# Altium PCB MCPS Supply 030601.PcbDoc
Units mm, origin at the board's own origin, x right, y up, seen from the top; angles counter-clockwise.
Board outline 142.99 x 138.8 mm, 2 copper layers (Top Layer, Bottom Layer); 73 components, 47 nets, 185 pads, 18 vias.
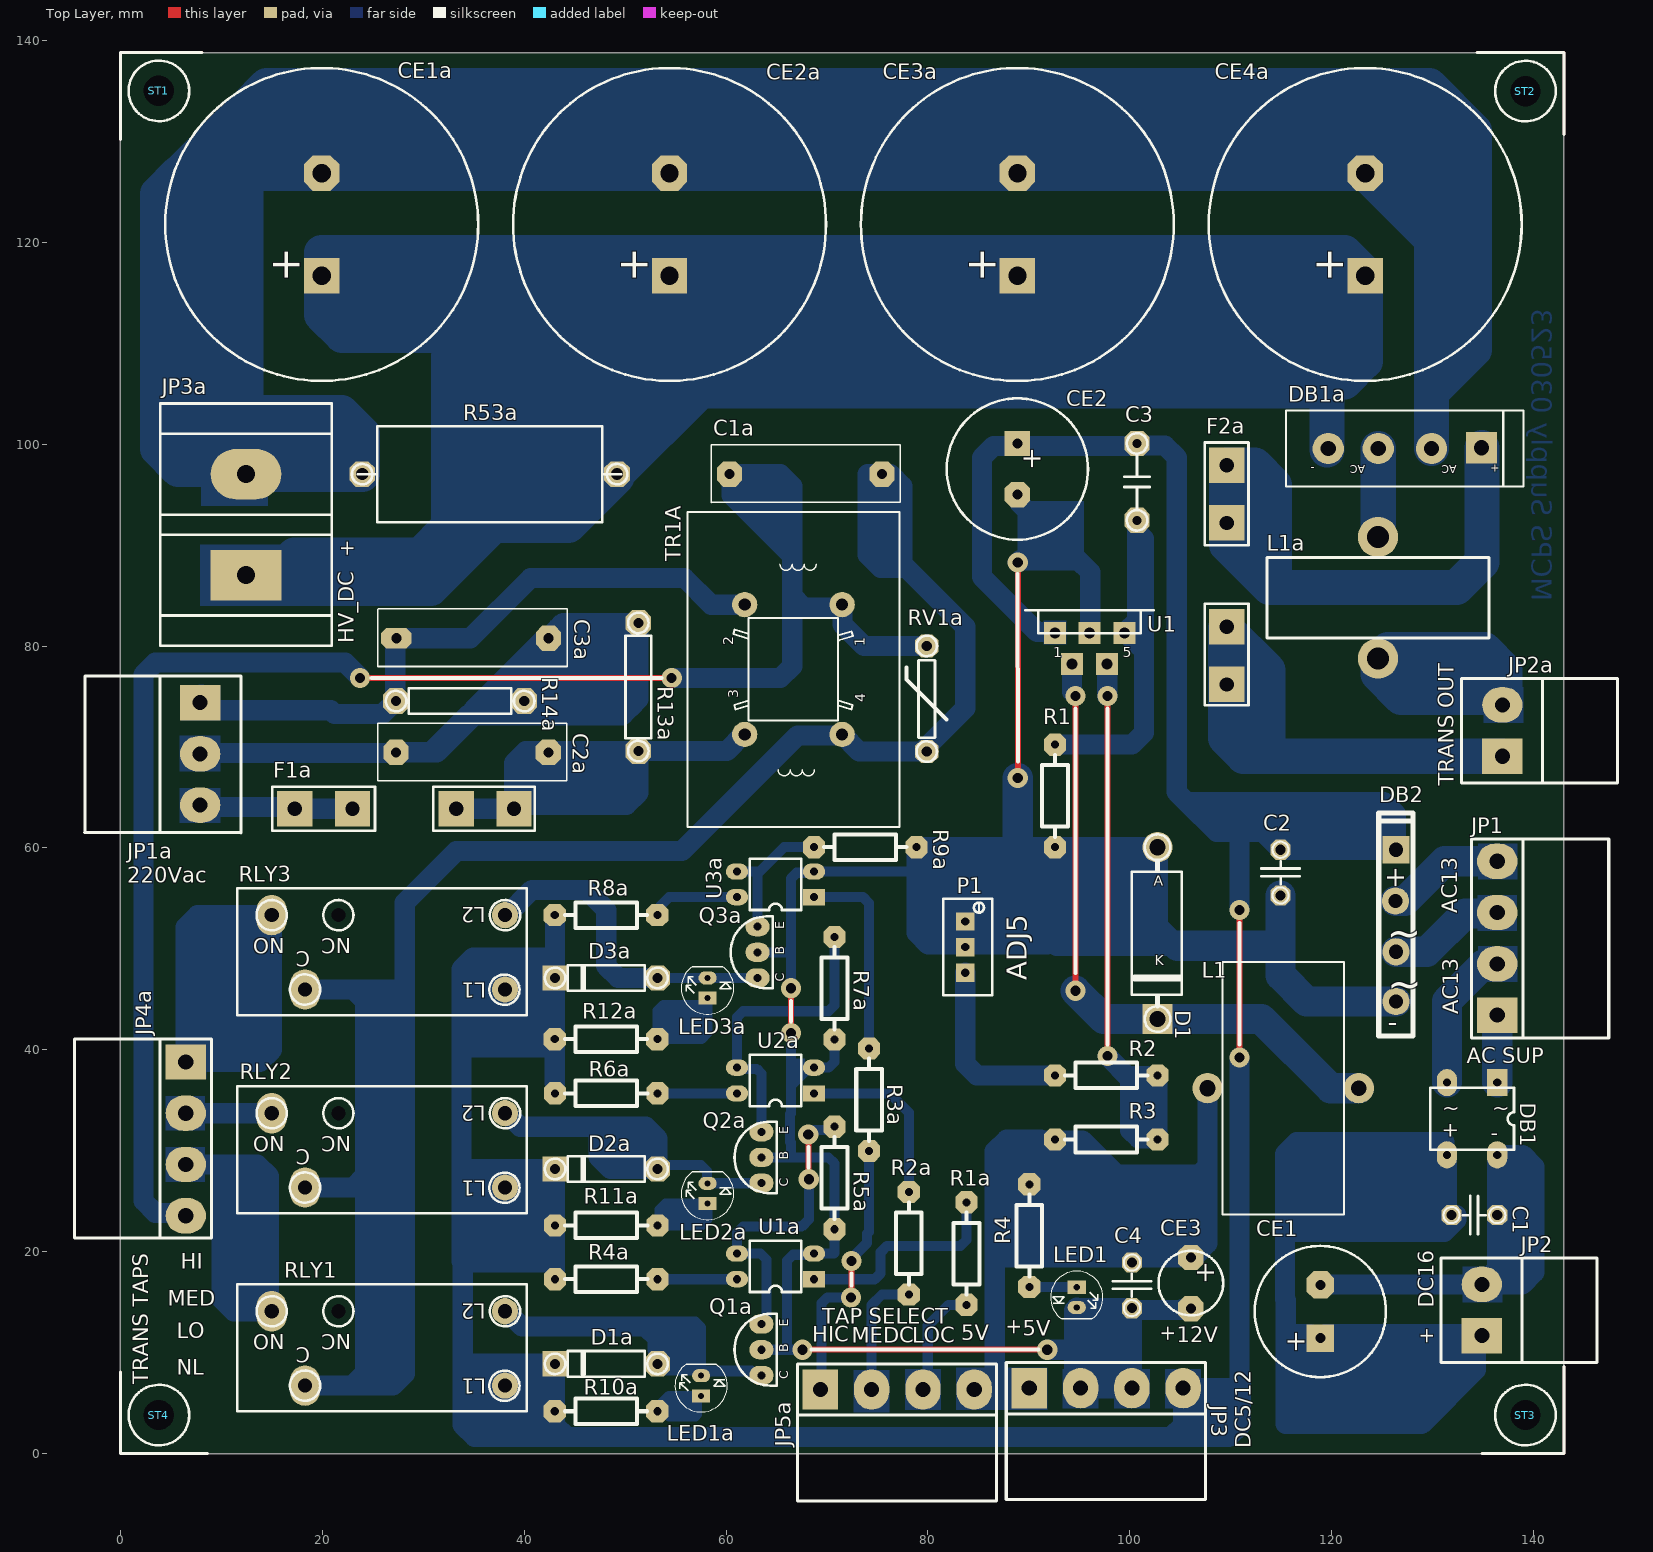
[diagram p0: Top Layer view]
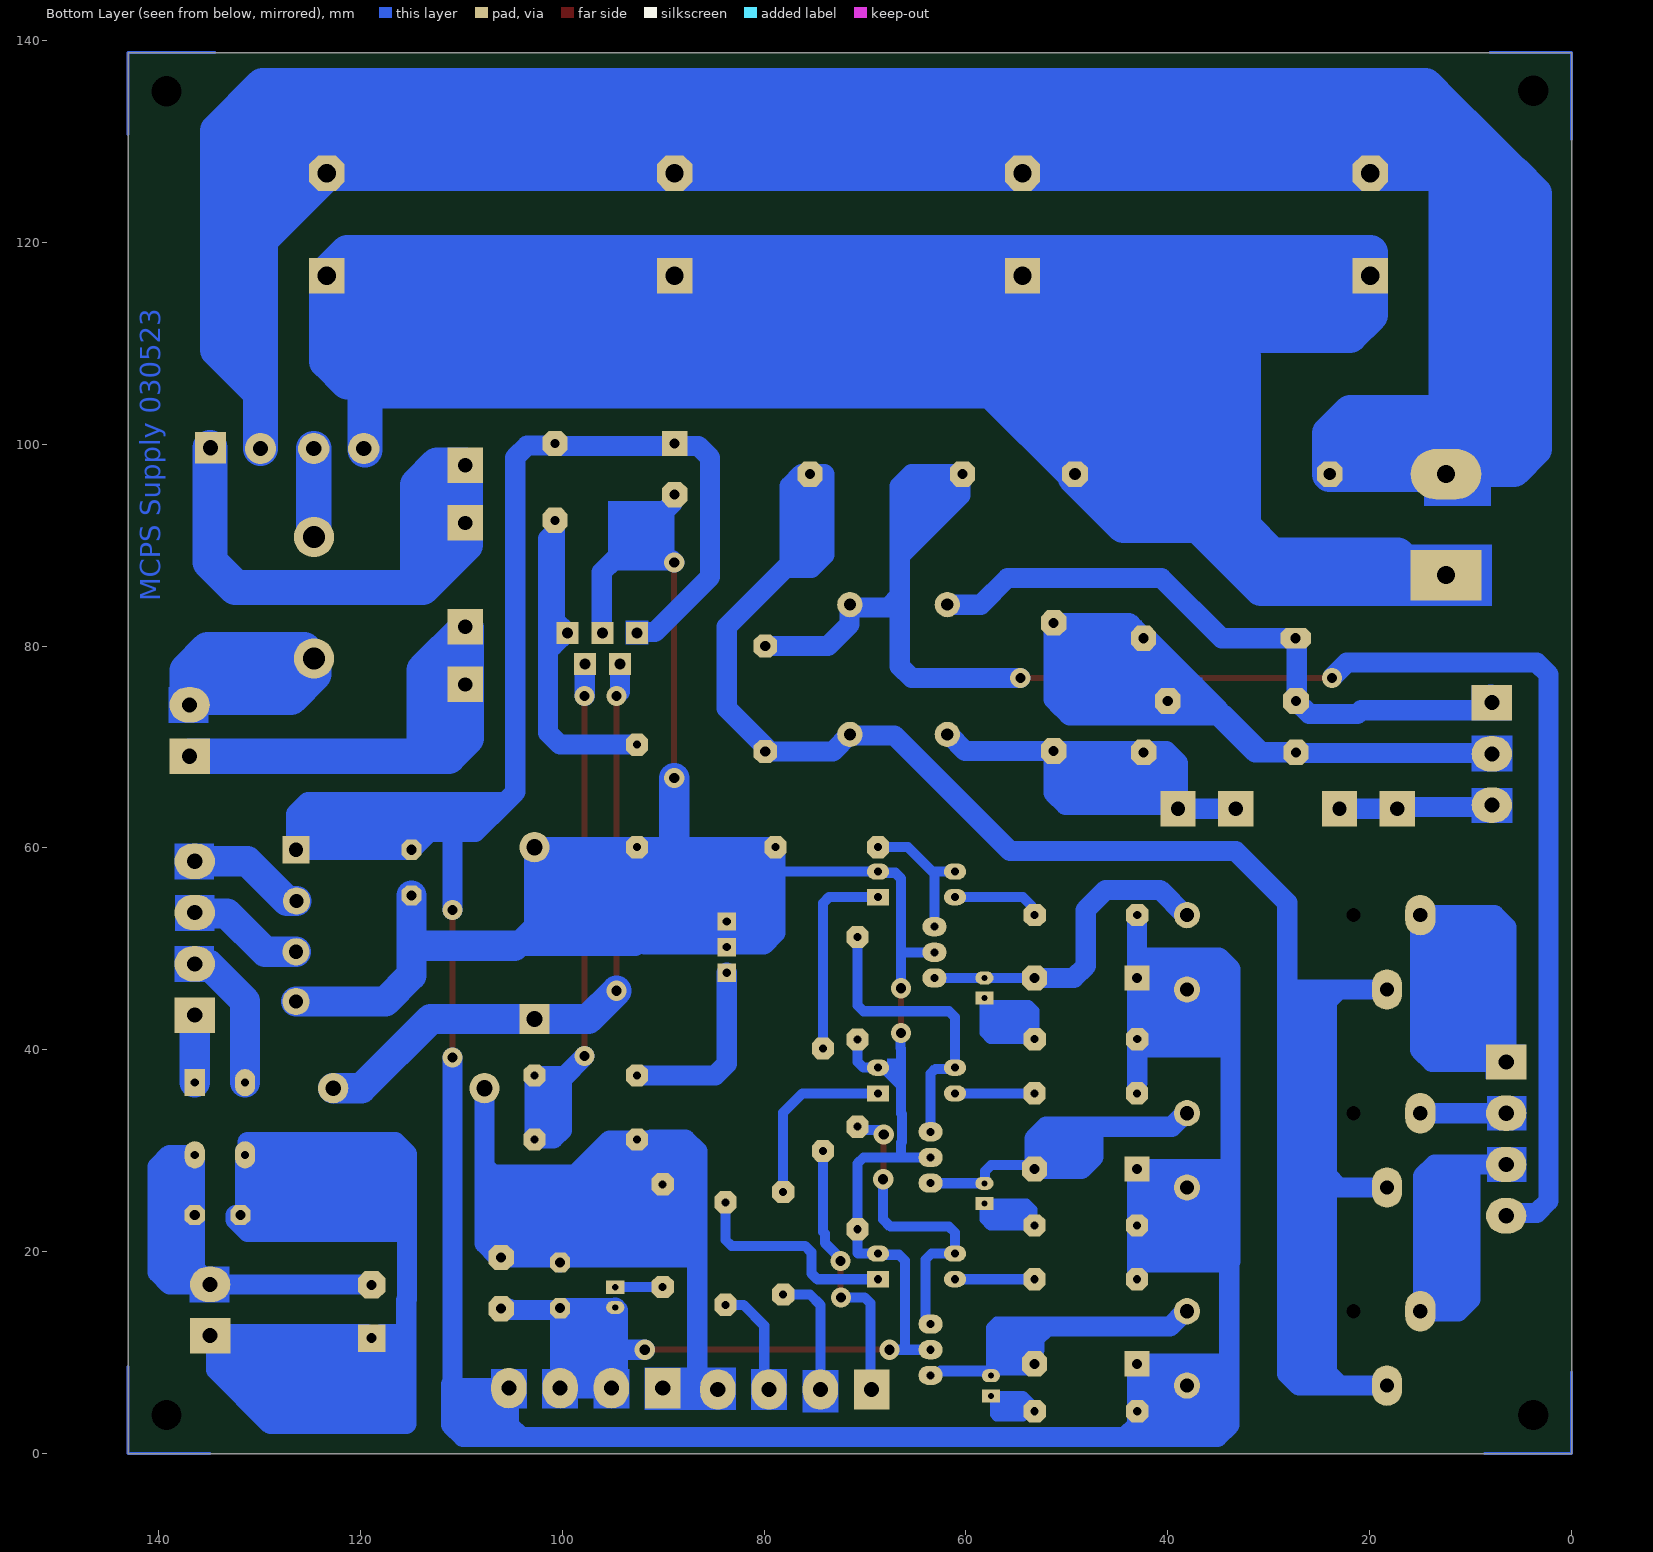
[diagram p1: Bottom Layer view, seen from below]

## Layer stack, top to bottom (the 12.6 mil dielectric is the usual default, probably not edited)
Top Solder: solder mask 0.0102, Solder Resist, Dk 3.5
Top Layer: signal copper 0.0356
Dielectric1: dielectric 0.32, FR-4, Dk 4.8
Bottom Layer: signal copper 0.0356
Bottom Solder: solder mask 0.0102, Solder Resist, Dk 3.5

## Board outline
0,0 142.989,0 142.989,138.797 0,138.797

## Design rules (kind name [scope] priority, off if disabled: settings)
Clearance [All] p1: gap=0.3 ignorepadtopadclearanceinfootprint=FALSE except(0.5: Arc-Arc Arc-Track Track-Track)
ComponentClearance [All] p1 off: gap=0.254 collisioncheckmode=3 verticalgap=0.254 showdistances=FALSE
PolygonConnect [All] p1: connectstyle=Direct reliefconductorwidth=1 reliefentries=4 polygonreliefangle="90 Angle" airgapwidth=0.3
RoutingVias [All] p1: holewidth=0.711 width=1.27 viastyle="Through Hole" minholewidth=0.711 minwidth=1.27 maxholewidth=0.711 maxwidth=1.27
SilkToSolderMaskClearance SilkscreenOverComponentPads [IsPad] p1: minsilkscreentomaskgap=0.254 clearancetoexposedcopper=TRUE
SolderMaskExpansion [All] p1: expansion=0.102 istentingtop=FALSE
UnRoutedNet [All] p1: checkbadconnections=TRUE
Width [All] p1: maxlimit=5 minlimit=0.3 preferedwidth=0.7 minimp=50.000000 maximp=50.000000 favimp=50.000000
27 further rules are at their usual default settings.

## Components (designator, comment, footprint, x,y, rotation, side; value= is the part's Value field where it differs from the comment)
C1 "100N" c1.8p 131.877,23.622 r0 top locked
C1a "47N/275" 47N/275#1 75.438,97.028 r0 top locked
C2 "100N" c1.8p 114.935,59.817 r270 top locked
C2a "47N/275" 47N/275#1 42.393,69.469 r0 top locked
C3 "100N" C3P 100.711,100.076 r270 top locked
C3a "47N/275" 47N/275#2 42.418,80.772 r0 top locked
C4 "100N" c1.8p 100.203,18.923 r270 top locked
CE1 "1000M/25" CAP1000M/25V 118.872,14.072 r180 top locked
CE1a "1200M/250V" "CAP 1200M/250" 19.939,121.766 r180 top locked
CE2 "2200M/25" "CAP 2200/25" 88.858,100.076 r0 top locked
CE2a "1200M/250V" "CAP 1200M/250" 54.398,121.766 r180 top locked
CE3 "1000M/63" CAP2P 106.045,19.431 r0 top locked
CE3a "1200M/250V" "CAP 1200M/250" 88.858,121.766 r180 top locked
CE4a "1200M/250V" "CAP 1200M/250" 123.317,121.766 r180 top locked
D1 "1N5822" d54 102.743,60.071 r0 top locked
D1a "1N5819" D4P 53.213,8.89 r0 top locked
D2a "1N5819" D4P 53.213,28.194 r0 top locked
D3a "1N5819" D4P 53.213,47.117 r0 top locked
DB1 "200V/1A" "BRG 1A" 133.909,33.172 r0 top locked
DB1a "600V/6A" "BRIDGE 6A" 127.254,99.568 r180 top locked
DB2 "200V/2A" "BRG GBU" 126.365,44.78 r0 top locked
F1a "1A5" FS 17.272,63.881 r0 top locked
F2a "5A" FS 109.601,97.917 r270 top locked
JP1 "AC SUP" 4EDG 136.398,43.434 r270 top locked
JP1a "220Vac" 3EDG-STR 7.874,74.422 r90 top locked
JP2 "DC16" 2edg-str 134.874,11.684 r270 top locked
JP2a "TRANS OUT" 2edg-str 136.906,69.088 r270 top locked
JP3 "DC5/12" 4EDG 90.043,6.477 r180 top locked
JP3a "HV_DC" DG55X2 12.446,87.028 r90 top locked
JP4a "TRANS TAPS" 4EDG 6.477,38.798 r90 top locked
JP5a "TAP SELECT" 4EDG 69.342,6.35 r180 top locked
L1 "100UH" "inductor 2512" 115.189,36.195 r0 top locked
L1a "10mH/5A" "INDUCTOR 2208" 124.587,90.805 r0 top locked
LED1 "Red" LED-5mm 94.752,16.478 r0 top locked
LED1a "LED" LED-5mm 57.521,5.715 r180 top locked
LED2a "LED" LED-5mm 58.156,24.765 r180 top locked
LED3a "LED" LED-5mm 58.156,45.117 r180 top locked
P1 "1K" "pot multi turn" 83.693,52.695 r180 top locked
Q1a "BC337" CBE-BC546 63.5,12.827 r180 top locked
Q2a "BC337" CBE-BC546 63.5,31.877 r180 top locked
Q3a "BC337" CBE-BC546 63.119,52.197 r180 top locked
R1 "10K%" R4P 92.583,70.231 r0 top locked
R1a "560R" R4P 83.82,24.892 r0 top locked
R2 "3K%" R4P 102.743,37.465 r270 top locked
R2a "560R" R4P 78.105,25.908 r0 top locked
R3 "10K%" R4P 92.583,31.115 r90 top locked
R3a "560R" R4P 74.168,40.132 r0 top locked
R4 "1K" R4P 90.043,26.67 r0 top locked
R4a "4K7" R4P 53.213,17.272 r270 top locked
R5a "10K" R4P 70.739,32.385 r0 top locked
R6a "4K7" R4P 53.213,35.687 r270 top locked
R7a "10K" R4P 70.739,51.181 r0 top locked
R8a "4K7" R4P 53.19,53.34 r270 top locked
R9a "10K" R4P 68.707,60.071 r90 top locked
R10a "1K8" R4P 43.03,4.191 r90 top locked
R11a "1K8" R4P 43.053,22.606 r90 top locked
R12a "1K8" R4P 43.03,41.053 r90 top locked
R13a "470K" R5P 51.308,69.596 r90 top locked
R14a "470K" R5P 40.005,74.549 r180 top locked
R53a "22K/5W" R5W 36.576,97.028 r0 top locked
RLY1 "12V/10A" RLY16D 26.543,10.414 r180 top locked
RLY2 "12V/10A" RLY16D 26.543,30.035 r180 top locked
RLY3 "12V/10A" RLY16D 26.543,49.657 r180 top locked
RV1a "250Vrms" "VARISTOR 3" 79.883,80.01 r0 top locked
ST1 "STUD" CORNER 0,138.811 r0 top locked
ST2 "STUD" CORNER 143.002,138.784 r270 top locked
ST3 "STUD" CORNER 143.002,0 r180 top locked
ST4 "STUD" CORNER 0,0 r90 top locked
TR1A "CMT" CMT1 71.501,71.247 r270 top locked
U1 "LM2576T-ADJ" PENTA1 92.583,81.28 r90 top locked
U1a "PC817" DIP4 68.707,17.272 r180 top locked
U2a "PC817" DIP4 68.707,35.687 r180 top locked
U3a "PC817" DIP4 68.707,55.118 r180 top locked

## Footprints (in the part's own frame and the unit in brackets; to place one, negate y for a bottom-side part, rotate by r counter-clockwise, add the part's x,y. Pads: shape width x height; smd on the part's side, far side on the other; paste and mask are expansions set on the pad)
2edg-str [mm]
  rect 3.5x4 hole 1.5: 1(0,0)
  oval 3.5x4 hole 1.5: 2(-5.08,0)
  silkscreen extent -7.7,-4.06 2.64,11.43
3EDG-STR [mm]
  rect 3.5x4 hole 1.5: 1(-0.025,-0.025)
  oval 3.5x4 hole 1.5: 2(-5.105,-0.025) 3(-10.185,-0.025)
  silkscreen extent -12.93,-4.09 2.62,11.41
4EDG [mm]
  rect 3.5x4 hole 1.5: 1(0,0)
  oval 3.5x4 hole 1.5: 2(-5.08,0) 3(-10.16,0) 4(-15.24,0)
  silkscreen extent -17.44,-2.54 2.29,11.05
47N/275#1 [mm]
  oct 2.5x2.5 hole 1: 1(0,0) 2(-15.088,0)
  silkscreen extent -16.92,-2.81 1.83,2.9
47N/275#2 [mm]
  oct 2.5x2.5 hole 1: 1(0,0)
  oct 3x2 hole 1: 2(-15.088,0)
  silkscreen extent -16.92,-2.81 1.83,2.9
"BRG 1A" [mm]
  rect 2x2.7 hole 0.8: 1(2.489,3.581)
  oval 2x2.7 hole 0.8: 2(2.489,-3.581) 3(-2.489,3.581) 4(-2.489,-3.581)
  silkscreen extent -4.15,-3.09 4.15,3.07
"BRG GBU" [mm]
  round 2.7 hole 1.4: 1(0,4.928) 2(0,0) 3(-0.051,9.957)
  rect 2.7x2.7 hole 1.4: 4(0,15.037)
  silkscreen extent -1.7,-3.41 1.7,18.69
"BRIDGE 6A" [mm]
  rect 3.1x3.1 hole 1.5: 1(-7.595,-0.076)
  round 3.1 hole 1.5: 2(-2.642,0) 3(2.642,0) 4(7.595,0)
  silkscreen extent -11.74,-3.75 11.76,3.75
c1.8p [mm]
  oct 2x2 hole 1: 1(0,0) 2(4.521,0)
  silkscreen extent -0.8,-1.91 5.32,1.9
C3P [mm]
  oct 2.5x2.5 hole 0.9: 1(0,0) 2(7.62,0)
  silkscreen extent -1.02,-1.27 8.64,1.27
CAP2P [mm]
  oct 2.5x2.5 hole 1: 1(0,0) 2(0,-5.08)
  silkscreen extent -3.2,-5.74 3.2,0.66
CAP1000M/25V [mm]
  rect 2.7x2.7 hole 1: 1(0,2.642)
  oct 2.7x2.7 hole 1: 2(0,-2.642)
  silkscreen extent -6.5,-6.5 6.5,6.5
"CAP 1200M/250" [mm]
  rect 3.5x3.5 hole 1.8: 1(0,5.08)
  oct 3.5x3.5 hole 1.8: 2(0,-5.08)
  silkscreen extent -15.5,-15.5 15.5,15.5
"CAP 2200/25" [mm]
  rect 2.5x2.5 hole 1: 1(0,0)
  oct 2.5x2.5 hole 1: 2(0,-5.08)
  silkscreen extent -7,-9.54 7,4.46
CBE-BC546 [mm]
  oval 2.4x1.9 hole 0.8: 1(0,2.54) 2(0,0) 3(0,5.08)
  silkscreen extent -1.52,-1.02 2.67,6.1
CMT1 [mm]
  round 2.5 hole 1.2: 1(-12.852,0) 2(-12.852,-9.652) 3(0,-9.652) 4(0,0)
  silkscreen extent -22.02,-15.34 9.17,5.69
CORNER [mm]
  round 2 hole 3: 1(3.81,-3.81)
  Multi-Layer lines w0.3: 0,-8.623 0,0.013 8.09,0.013
  silkscreen extent 0,-8.62 8.09,0.01
D4P [mm]
  oct 2.5x2.5 hole 1: 1(0,0)
  rect 2.5x2.5 hole 1: 2(-10.16,0)
  silkscreen extent -11.17,-1.27 1.02,1.27
d54 [mm]
  round 3 hole 1.6: 1(0,0)
  rect 3x3 hole 1.6: 2(0,-17.018)
  silkscreen extent -2.54,-18.29 2.41,1.27
DG55X2 [mm]
  rect 5x7 hole 1.8: 1(0,0)
  oval 5x7 hole 1.8: 2(10,0)
  silkscreen extent -7,-8.5 17,8.5
DIP4 [mm]
  rect 2.2x1.6 hole 0.8: 1(0,0)
  oval 2.2x1.6 hole 0.8: 2(0,-2.54) 3(7.62,-2.54) 4(7.62,0)
  silkscreen extent 1.27,-3.81 6.35,1.27
FS [mm]
  rect 3.5x3.5 hole 1.4: 1(0,0) 2(21.717,0) ""(5.715,0) ""(16.002,0)
  silkscreen extent -2.25,-2.16 23.76,2.16
"INDUCTOR 2208" [mm]
  round 4 hole 2.2: 1(0,0) 2(0,-12.04)
  silkscreen extent -11,-10.01 11,-2.03
"inductor 2512" [mm]
  round 3 hole 1.6: 1(-7.493,0)
  round 3 hole 1.5: 2(7.493,0)
  silkscreen extent -6.02,-12.52 6.02,12.52
LED-5mm [mm]
  rect 1.8x1.3 hole 0.6: 1(-0.01,0)
  oval 1.8x1.3 hole 0.6: 2(-0.01,-2)
  silkscreen extent -2.61,-3.13 2.59,1.6
PENTA1 [mm]
  rect 2.2x2.2 hole 1.1: 1(0,0) 2(-3.048,-1.702) 3(0,-3.429) 4(-3.048,-5.156) 5(0,-6.883)
  silkscreen extent 0,-9.78 2.29,2.92
"pot multi turn" [mm]
  rect 1.8x1.8 hole 0.8: 1(0,5.06) 2(0,0) 3(0,2.53)
  silkscreen extent -2.67,-2.29 2.18,7.29
R4P [mm]
  oct 2.2x2.2 hole 0.8: 1(0,0) 2(0,-10.16)
  silkscreen extent -1.27,-9.14 1.27,-1.02
R5P [mm]
  oct 2.54x2.54 hole 1: 1(0,0) 2(12.7,0)
  silkscreen extent -1.02,-1.27 13.72,1.27
R5W [mm]
  oct 2.54x2.54 hole 1.2: 1(-12.624,0) 2(12.624,0)
  silkscreen extent -13.64,-4.75 13.64,4.75
RLY16D [mm]
  oval 3x4 hole 1.4: 1(8.255,3.683) 2(11.557,-3.683)
  round 1 hole 1.4: 3(4.953,-3.683)
  round 2.6 hole 1.4: 4(-11.557,-3.683) 5(-11.557,3.683)
  silkscreen extent -13.72,-6.35 14.99,6.22
"VARISTOR 3" [mm]
  oct 2.3x2.3 hole 1: 1(0,-10.465) 2(0,0)
  silkscreen extent -2.01,-11.48 1.95,1.02

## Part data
C1 C1a C2 C2a C3 C3a C4: library part C
CE1 CE1a CE2 CE2a CE3 CE3a CE4a: library part E
D1: library part Diode, "Default Diode"
D1a D2a D3a: library part D
DB1 DB1a DB2: library part BRIDGE
F1a F2a: library part FUSE1
JP1 JP3 JP4a JP5a: library part "Header 4", "Header, 4-Pin"
JP1a: library part "Header 3", "Header, 3-Pin"
JP2 JP2a JP3a: library part "Header 2", "Header, 2-Pin"
L1: library part "INDUCTOR IRON"
L1a: library part INDUCTOR
LED1: library part LED, "LED"
LED1a LED2a LED3a: "LED LIGHTING"
P1: library part POT2
Q1a Q2a Q3a: library part N
R1 R1a R2 R2a R3 R3a R4 R4a R5a R6a R7a R8a R9a R10a R11a R12a R13a R14a R53a: library part R
RLY1 RLY2 RLY3: library part RELAY-SPST4
RV1a: library part VARISTOR
TR1A: library part TRANS1
U1: library part LM2576
U1a U2a U3a: library part OPTODIP4

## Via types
v1: diameter 2, hole 1, Top Layer to Bottom Layer, 18 vias

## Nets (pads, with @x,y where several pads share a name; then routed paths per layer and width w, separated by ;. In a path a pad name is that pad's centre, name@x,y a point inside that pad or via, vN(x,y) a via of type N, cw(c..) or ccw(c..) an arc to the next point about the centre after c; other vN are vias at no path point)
5V: C4.1 CE3.1 JP3.1 JP5a.4 L1.1 R3.1 R4.1 | length 132.3
  Bottom Layer w2: JP5a.4 84.645,6.413 86.868,6.413 ; 86.868,6.858 89.662,6.858 JP3.1 ; 87.312,6.413 86.614,7.112 86.614,19.177 ; 91.191,31.115 87.786,31.115 86.614,29.943 86.614,25.398 ; 96.462,23.79 94.615,25.636 94.615,31.015 ; L1.1 107.696,28.448 ; 86.614,19.177 86.614,25.398 ; 86.614,19.177 86.868,19.431 93.726,19.431 ; 86.614,25.398 87.786,26.57 89.943,26.57 R4.1 ; R4.1 90.019,26.694 90.019,29.843 91.191,31.015 92.483,31.015 R3.1 92.683,31.015 94.615,31.015 ; R4.1 90.043,23.114 93.726,19.431 ; 93.726,19.431 99.695,19.431 C4.1 ; 94.615,31.015 95.326,31.015 98.726,27.615 100.203,27.615 ; C4.1 100.203,25.781 ; C4.1 100.711,19.431 105.795,19.431 105.918,19.554 105.918,19.558 CE3.1 106.256,19.642 106.524,19.642 107.696,20.813 107.696,25.781 ; 100.203,25.781 100.203,27.615 ; 100.203,25.781 107.696,25.781 ; 100.203,27.615 106.863,27.615 107.696,28.448 ; 107.696,25.781 107.696,28.448
12V: C2.1 C3.1 CE2.1 D1a.2 D2a.2 D3a.2 DB2.4 JP3.4 R4a.2 R6a.2 R8a.2 R10a.1 R11a.1 R12a.1 RLY1.5 RLY2.5 RLY3.5 U1.1 | length 451.3
  Top Layer w0.6: v1(110.871,39.243) v1(110.871,53.848)
  Bottom Layer w2: RLY1.5 38.1,5.363 39.272,4.191 ; R8a.2 43.042,53.328 43.042,49.022 ; R12a.1@43.042,41.053 43.042,47.117 39.405,47.117 38.262,45.974 RLY3.5 38.1,42.224 39.272,41.053 R12a.1 ; D3a.2@43.042,47.882 43.042,49.022 ; R4a.2 43.053,18.923 ; R6a.2 43.053,36.703 43.03,36.726 R12a.1 ; U1.1 92.483,81.38 90.832,81.38 85.344,86.868 85.344,98.654 86.516,99.826 88.608,99.826 CE2.1 89.108,99.826 90.193,99.826 90.197,99.822 100.418,99.822 100.672,100.076 C3.1 100.922,99.865 103.476,99.865 104.648,98.694 104.648,65.532 105.639,64.541 ; v1(110.871,39.243) 110.871,6.731 ; v1(110.871,53.848) 110.871,61.595 ; 110.998,6.477 110.998,2.823 109.826,1.651 104.111,1.651 ; 110.998,6.858 110.871,6.731 ; 33.782,23.778 33.782,28.321 ; 33.782,23.778 33.782,19.05 33.909,18.923 ; 33.782,23.778 34.954,22.606 39.272,22.606 ; 33.782,28.321 33.909,28.194 D2a.2 ; 33.782,28.321 33.782,40.259 ; 33.782,40.259 33.782,47.977 34.954,49.149 42.915,49.149 43.042,49.022 ; 33.782,40.259 42.236,40.259 R12a.1 ; 33.909,5.236 33.909,2.823 35.081,1.651 44.225,1.651 ; 33.909,5.236 34.954,4.191 39.272,4.191 ; 33.909,5.236 33.909,9.398 ; 33.909,9.398 34.417,8.89 D1a.2 ; 33.909,9.398 33.909,18.923 ; 33.909,18.923 43.053,18.923 ; 39.272,4.191 R10a.1 R10a.1@43.042,4.202 ; 39.272,22.606 R11a.1 ; 39.272,22.606 38.1,23.778 RLY2.5 38.215,26.467 40.056,26.467 41.572,27.983 42.842,27.983 D2a.2 ; R10a.1@43.042,4.202 R10a.1@43.053,4.214 ; R10a.1@43.042,4.202 43.042,8.879 D1a.2 ; R10a.1@43.053,4.214 43.053,2.823 44.225,1.651 ; R10a.1@43.053,4.214 D1a.2 ; 43.053,18.923 R11a.1 ; R11a.1 D2a.2 ; 44.225,1.651 104.111,1.651 ; 104.111,1.651 105.283,2.823 JP3.4 110.617,6.477 110.871,6.731 ; 105.639,64.541 125.193,64.541 126.365,63.37 DB2.4 C2.1 113.157,61.595 110.871,61.595 ; 105.639,64.541 108.585,61.595 110.871,61.595
16V: C1.1 CE1.1 DB1.4 JP2.1 | length 124.7
  Bottom Layer w2: 118.745,25.4 115.372,22.027 ; 121.391,27.571 124.956,27.571 126.365,26.162 ; 121.856,29.654 123.063,30.861 ; DB1.4@131.07,29.941 131.42,29.941 DB1.4 131.42,24.079 C1.1 ; DB1.4@131.162,30.861 123.063,30.861 ; C1.1@132.334,23.622 132.334,23.143 131.162,21.971 115.824,21.971 115.372,21.519 ; 115.372,21.519 115.372,22.027 ; 115.372,21.519 115.372,15.263 115.443,15.192 115.443,11.811 ; 115.372,22.027 115.372,29.689 116.544,30.861 123.063,30.861 ; 115.443,11.811 115.443,2.921 128.905,2.921 134.275,8.291 134.275,11.085 JP2.1 134.874,11.811 119.342,11.811 118.961,11.43 CE1.1 118.611,11.691 118,11.691 117.88,11.811 115.443,11.811
ERTH: C2a.2 C3a.1 JP1a.2 R13a.2 R14a.1 | length 105.4
  Bottom Layer w2: JP1a.2 7.976,69.393 27.229,69.393 C2a.2 30.734,69.469 ; 34.989,73.723 37.37,76.105 40.005,78.74 ; 35.306,73.406 31.369,69.469 30.734,69.469 ; C3a.1 42.207,80.561 41.826,80.561 40.957,79.692 40.005,78.74 ; C3a.1@42.629,80.983 42.629,81.085 43.319,81.776 43.84,82.296 R13a.2@51.259,82.296 ; R13a.2 51.308,75.721 ; 30.734,69.469 34.417,73.152 35.56,73.152 39.878,73.152 ; 39.878,73.152 49.755,73.152 50.136,73.533 ; 39.878,73.152 40.259,73.533 50.136,73.533 ; 40.005,78.74 R14a.1 50.136,74.549 50.8,75.213 51.308,75.721 ; 50.136,73.533 50.644,74.041 51.308,74.705 51.308,75.721
GND5: C2.2 C4.2 CE2.2 CE3.2 D1.1 DB2.2 JP3.2 JP3.3 LED1.2 P1.2 P1.3 Q1a.1 Q2a.1 Q3a.1 R1.2 R5a.2 R7a.2 R9a.2 U1.3 U1a.2 U2a.2 U3a.2 | length 305.3
  Top Layer w0.6: v1(66.421,41.656) v1(66.421,46.101) ; v1(67.564,10.287) v1(91.821,10.287) ; v1(88.9,66.929) v1(88.9,88.265)
  Bottom Layer w1: Q3a.1 66.294,49.657 ; Q1a.1 66.04,10.287 ; Q2a.1 66.421,29.337 ; v1(66.421,41.656) 66.473,41.604 66.473,40.161 66.421,40.11 66.421,36.432 ; v1(66.421,46.101) 66.421,49.53 66.294,49.657 ; v1(67.564,10.287) 66.04,10.287 ; R7a.2 70.739,38.813 70.153,38.227 U2a.2 68.592,38.112 68.101,38.112 66.421,36.432 ; 78.867,57.658 U3a.2 68.592,57.543 67.007,57.543 66.421,56.957 66.421,49.784 66.294,49.657 ; 94.107,10.287 94.488,10.668 ; U1.3 U1.3@96.071,81.221 ; 66.04,10.287 66.04,19.111 66.626,19.697 68.592,19.697 U1a.2 70.7,19.812 70.739,19.851 R5a.2 70.739,28.751 70.153,29.337 66.421,29.337 ; 66.421,29.337 66.421,30.801 66.345,30.877 66.345,33.617 66.421,33.693 66.421,36.432
  Bottom Layer w2: CE2.2 89.068,94.785 89.068,94.141 92.148,91.061 92.148,90.794 ; v1(88.9,88.265) 89.138,88.503 89.858,88.503 92.148,90.794 ; 89.154,57.785 88.9,58.039 88.9,60.071 ; 91.812,50.419 80.039,50.419 78.867,51.591 78.867,57.658 R9a.2 88.9,60.071 ; v1(91.821,10.287) 94.107,10.287 ; 92.148,90.927 92.148,90.794 ; 92.583,52.705 92.583,54.737 ; 92.724,50.316 104.751,50.316 102.761,52.306 102.761,60.053 D1.1 R1.2 ; LED1.2@94.742,14.402 C4.2 ; LED1.2 94.488,14.224 94.488,10.668 94.488,7.768 95.123,7.133 JP3.2 JP3.3 100.203,6.858 100.33,6.985 100.203,7.112 100.203,14.224 105.156,14.224 105.283,14.351 CE3.2 ; 94.964,55.067 94.818,55.067 94.488,54.737 92.583,54.737 ; 96.083,82.55 96.083,87.331 94.911,88.503 94.439,88.503 92.148,90.794 ; 114.262,50.316 114.935,49.644 ; 88.9,60.071 R1.2 ; 92.583,54.737 R1.2
  Bottom Layer w3: 88.9,60.071 v1(88.9,66.929) ; 104.751,50.316 114.262,50.316 ; C2.2 114.935,49.644 114.935,47.371 117.526,44.78 DB2.2
HI: JP4a.1 RLY3.2 | length 44.7
  Bottom Layer w2: JP4a.1 13.814,38.798 14.986,39.97 RLY3.2 7.649,53.34 6.477,52.168 JP4a.1
HIC: JP5a.1 R3a.2 | length 27
  Top Layer w0.6: v1(72.39,15.472) 72.416,15.498 72.416,19.046 v1(72.442,19.072)
  Bottom Layer w1: JP5a.1 69.462,6.47 69.462,14.886 70.048,15.472 v1(72.39,15.472) ; v1(72.442,19.072) 72.442,19.343 73.977,20.878 73.977,21.78 74.168,21.971 R3a.2
HV: CE1a.1 CE2a.1 CE3a.1 CE4a.1 DB1a.4 JP3a.1 R53a.2 | length 462.5
  Bottom Layer w3.5: 30.797,112.286 32.639,110.444 32.639,107.315 ; 32.512,89.078 32.512,91.821 ; 71.247,115.252 52.763,111.995 52.403,111.995 49.276,112.091 ; DB1a.4@119.536,99.441 119.536,106.172 ; 32.512,91.821 32.512,107.315 32.512,108.712 39.306,108.712 49.276,108.712 49.276,112.091 ; 32.512,91.821 29.718,89.027 17.246,89.027 16.497,88.278 15.196,88.278 13.946,87.028 JP3a.1 13.696,85.778 17.193,85.778 17.246,85.725 30.734,85.725 36.957,91.948 44.374,91.948 49.2,96.774 R53a.2 57.455,105.283 118.647,105.283 119.536,106.172 ; 49.276,112.091 34.544,112.542 34.544,110.762 21.989,110.762 19.939,112.813 19.939,118.981 121.023,118.981 ; 49.276,112.091 49.276,116.178 48.768,116.686 CE2a.1 71.247,116.686 CE3a.1 CE4a.1@121.586,116.686 ; 119.536,106.172 121.267,106.172 123.317,108.222 123.317,116.93 121.267,118.981 121.023,118.981 ; 119.536,106.172 119.536,114.636 CE4a.1@121.586,116.686 ; 121.023,118.981 CE4a.1 CE4a.1@121.586,116.686
LO: JP4a.3 RLY1.2 | length 41
  Bottom Layer w2: JP4a.3 10.033,28.639 ; 10.033,28.639 13.56,28.639 14.732,27.467 14.732,15.558 14.795,15.495 14.795,14.288 RLY1.2 11.205,14.097 10.033,15.269 10.033,28.639
LOC: JP5a.3 R1a.2 | length 11.2
  Bottom Layer w1: JP5a.3 79.98,6.828 79.98,12.67 82.042,14.732 R1a.2
MED: JP4a.2 RLY2.2 | length 8.5
  Bottom Layer w2: JP4a.2 RLY2.2
MEDC: JP5a.2 R2a.2 | length 12.5
  Bottom Layer w1: JP5a.2 74.422,14.732 75.438,15.748 R2a.2
NetC1_2: C1.2 CE1.2 DB1.2 JP2.2 | length 49.9
  Bottom Layer w2: CE1.2 118.897,16.739 133.96,16.739 134.112,16.891 134.239,16.764 JP2.2 ; JP2.2 138.909,16.764 140.081,17.936 140.081,28.419 138.909,29.591 DB1.2 C1.2 136.398,18.288 JP2.2
NetC2a_1: C2a.1 F1a.2 F1a.@33.274,63.881 R13a.1 TR1A.3 | length 56.6
  Bottom Layer w2: F1a.@33.274,63.881 F1a.2 ; C2a.1 42.405,69.456 42.405,64.275 42.418,64.262 ; R13a.1@51.301,69.589 51.301,65.434 50.13,64.262 42.418,64.262 ; TR1A.3 61.714,71.247 60.063,69.596 R13a.1 40.161,69.596 38.989,68.424 F1a.2 ; F1a.2 39.116,63.881 39.497,64.262 42.418,64.262
NetC3_2: C3.2 R1.1 U1.5 | length 44.5
  Bottom Layer w2: R1.1 92.57,70.244 100.23,70.244 101.402,71.415 101.402,80.008 ; U1.5 U1.5@99.554,81.367 ; C3.2@100.711,92.417 C3.2@100.711,91.313 ; 101.346,83.16 100.711,82.525 ; U1.5@99.554,81.367 100.913,80.008 101.402,80.008 ; U1.5@99.554,81.367 100.711,82.525 ; 100.711,82.525 C3.2@100.711,91.313 ; C3.2@100.711,91.313 101.402,90.622 101.402,83.16 101.402,80.008
NetC3a_2: C3a.2 JP1a.1 R14a.2 TR1A.2 | length 64.8
  Bottom Layer w2: JP1a.1 8.649,73.647 20.841,73.647 21.209,73.279 25.986,73.279 27.256,74.549 R14a.2 27.229,74.625 27.229,80.67 C3a.2 ; C3a.2@27.37,80.772 34.671,80.772 40.64,86.741 55.88,86.741 58.522,84.099 TR1A.2
  Bottom Layer w3.5: JP1a.1 7.976,74.397 JP1a.1@8.001,74.422
NetD1_2: D1.2 L1.2 U1.2 | length 64.6
  Top Layer w0.6: v1(94.615,45.847) v1(94.615,75.057)
  Bottom Layer w1: v1@94.28,75.465 94.615,75.13 v1(94.615,75.057) ; U1.2@94.28,78.227 U1.2
  Bottom Layer w2: v1@94.28,75.465 U1.2@94.28,78.227
  Bottom Layer w3: v1(94.615,45.847) 97.409,43.053 D1.2 113.03,43.053 119.888,36.195 L1.2
NetD1a_1: D1a.1 LED1a.2 Q1a.3 RLY1.4 | length 46.5
  Bottom Layer w1: 51.53,13.081 56.945,13.081 57.531,12.495 LED1a.2@57.531,8.215 ; 53.213,10.287 D1a.1 53.802,8.301 56.945,8.301 LED1a.2@57.031,8.215 ; Q1a.3 63.006,7.747 Q1a.3@62.625,8.128 ; LED1a.2@57.031,8.215 LED1a.2 ; LED1a.2@57.031,8.215 LED1a.2@57.531,8.215 ; LED1a.2 LED1a.2@57.531,8.215 ; LED1a.2 57.862,7.715 58.275,8.128 Q1a.3@62.625,8.128 ; LED1a.2@57.531,8.215 62.538,8.215 Q1a.3@62.625,8.128
  Bottom Layer w2: RLY1.4 38.262,14.097 39.786,12.573 52.041,12.573 53.213,11.401 53.213,10.287
NetD2a_1: D2a.1 LED2a.2 Q2a.3 RLY2.4 | length 40.3
  Bottom Layer w1: D2a.1 53.594,28.575 57.514,28.575 58.1,27.989 58.1,26.831 LED2a.2 58.182,26.781 63.484,26.781 Q2a.3
  Bottom Layer w2: RLY2.4 38.262,33.718 39.596,32.385 52.041,32.385 53.213,31.213 D2a.1 48.543,28.194 47.371,29.366 47.371,32.258
NetD3a_1: D3a.1 LED3a.2 Q3a.3 RLY3.4 | length 32.9
  Bottom Layer w1: D3a.1 LED3a.2 Q3a.3
  Bottom Layer w2: RLY3.4 38.262,53.34 40.762,55.84 46.152,55.84 48.133,53.859 48.133,48.289 49.305,47.117 D3a.1
NetDB1_1: DB1.1 JP1.1 | length 6.7
  Bottom Layer w3: DB1.1 JP1.1
NetDB1_3: DB1.3 JP1.2 | length 14.6
  Bottom Layer w3: DB1.3 131.42,44.82 135.018,48.418 136.302,48.418 JP1.2
NetDB1a_1: DB1a.1 F2a.1 F2a.@109.601,92.202 | length 63.2
  Bottom Layer w3.5: DB1a.1@134.896,99.644 134.896,88.33 132.37,85.805 113.839,85.805 ; 113.839,85.805 114.339,86.305 114.339,95.954 112.377,97.917 F2a.1 109.601,92.202 109.601,90.043 113.839,85.805
NetDB1a_3: DB1a.3 L1a.1 | length 8.8
  Bottom Layer w3.5: L1a.1 124.612,90.83 DB1a.3
NetDB2_1: DB2.1 JP1.3 | length 11.6
  Bottom Layer w3: DB2.1 129.418,49.708 133.208,53.498 136.302,53.498 JP1.3
NetDB2_3: DB2.3 JP1.4 | length 11.7
  Bottom Layer w3: DB2.3 127.254,54.737 131.191,58.674 JP1.4
NetF1a_1: F1a.1 F1a.@22.987,63.881 JP1a.3 | length 15.2
  Bottom Layer w2: JP1a.3 7.912,64.249 8.103,64.059 17.094,64.059 F1a.1 F1a.@22.987,63.881
NetF2a_2: F2a.2 F2a.@109.601,81.915 JP2a.1 | length 53.7
  Bottom Layer w3.5: F2a.@109.601,81.915 F2a.@109.474,81.788 ; JP2a.1 114.935,69.088 113.665,69.088 ; F2a.@109.474,81.788 113.665,77.597 113.665,69.088 ; F2a.@109.474,81.788 109.474,80.137 109.474,76.2 109.474,70.884 111.27,69.088 113.665,69.088
NetJP2a_2: JP2a.2 L1a.2 | length 32.6
  Bottom Layer w3.5: L1a.2@124.587,77.23 126.887,74.93 135.894,74.93 136.656,74.168 137.156,74.168 137.156,74.668 137.167,74.679 137.167,77.579 135.117,79.629 125.586,79.629 124.722,78.765 L1a.2 L1a.2@124.587,77.23
NetLED1_1: LED1.1 R4.2 | length 4.7
  Bottom Layer w1: R4.2 90.059,16.494 94.726,16.494 LED1.1
NetLED1a_1: LED1a.1 R10a.2 | length 13.2
  Bottom Layer w1: LED1a.1 54.376,5.715 53.533,4.872 53.533,4.534 R10a.2 53.533,3.848 54.211,3.848 54.376,3.683 55.499,3.683 ; 55.499,3.683 56.409,4.593 57.131,5.315 57.131,3.869 56.945,3.683 55.499,3.683
NetLED2a_1: LED2a.1 R11a.2 | length 13.4
  Bottom Layer w1: R11a.2 53.411,22.804 53.411,24.179 53.997,24.765 LED2a.1 58.166,23.192 57.58,22.606 R11a.2
NetLED3a_1: LED3a.1 R12a.2 | length 16.8
  Bottom Layer w1: LED3a.1 58.166,44.323 ; 58.166,44.323 58.166,41.656 57.563,41.053 R12a.2 53.213,41.076 53.213,43.864 53.799,44.45 58.039,44.45 58.166,44.323
NetP1_1: P1.1 R2.2 | length 18.4
  Bottom Layer w2: P1.1 83.693,38.608 84.836,37.465 R2.2
NetQ1a_2: Q1a.2 R5a.1 U1a.3 | length 30.9
  Top Layer w0.6: v1(68.145,31.623) 68.145,27.232 v1(68.199,27.178)
  Bottom Layer w1: Q1a.2 63.506,12.827 63.922,13.243 63.922,13.249 64.008,13.335 64.008,19.226 63.422,19.812 U1a.3 61.087,21.893 61.673,22.479 67.486,22.479 68.199,23.192 v1(68.199,27.178) ; v1(68.145,31.623) 68.564,32.042 70.396,32.042 R5a.1
NetQ2a_2: Q2a.2 R7a.1 U2a.3 | length 30.3
  Bottom Layer w1: Q2a.2 63.5,37.641 63.029,38.112 61.202,38.112 U2a.3 61.087,43.229 61.673,43.815 70.153,43.815 70.739,44.401 R7a.1
NetQ3a_2: Q3a.2 R9a.1 U3a.3 | length 14.2
  Bottom Layer w1: U3a.3 63.324,57.658 ; Q3a.2 63.119,57.453 63.324,57.658 ; R9a.1 65.737,60.071 63.324,57.658
NetR1a_1: R1a.1 U1a.1 | length 21.7
  Bottom Layer w1: U1a.1 74.725,17.272 75.311,17.858 75.311,19.939 75.946,20.574 83.234,20.574 83.82,21.16 R1a.1
NetR2_1: R2.1 R3.2 U1.4 | length 64.6
  Top Layer w0.6: v1(97.79,39.37) v1(97.79,75.057)
  Bottom Layer w1: v1@97.765,75.082 v1(97.79,75.057) ; U1.4@97.765,78.157 U1.4@97.789,78.182 ; 100.041,35.404 101.155,34.29 102.743,34.29
  Bottom Layer w2: U1.4 97.789,78.182 U1.4@97.839,78.132 ; v1@97.765,75.082 U1.4@97.765,78.157 ; v1(97.79,39.37) 100.013,37.148 ; 100.013,37.148 100.273,37.408 100.908,37.408 ; 100.013,37.148 100.013,36.512 100.041,36.541 ; 100.013,37.148 100.041,37.119 100.041,36.541 ; 100.041,36.541 100.908,37.408 ; 100.041,36.541 100.041,35.404 100.041,32.039 100.865,31.215 102.643,31.215 R3.2 102.743,34.29 R2.1 102.686,37.408 100.908,37.408
NetR2a_1: R2a.1 U2a.1 | length 18.1
  Bottom Layer w1: U2a.1 76.2,35.687 78.105,33.782 R2a.1
NetR3a_1: R3a.1 U3a.1 | length 20.1
  Bottom Layer w1: U3a.1 73.582,55.118 74.168,54.532 R3a.1
NetR4a_1: R4a.1 U1a.4 | length 7.9
  Bottom Layer w1: R4a.1 U1a.4
NetR6a_1: R6a.1 U2a.4 | length 7.9
  Bottom Layer w1: R6a.1 U2a.4
NetR8a_1: R8a.1 U3a.4 | length 9
  Bottom Layer w1: R8a.1 53.533,53.683 53.533,54.296 54.355,55.118 U3a.4
NL: C1a.2 JP4a.4 RV1a.2 TR1A.1 | length 174.5
  Top Layer w0.6: v1(23.749,76.835) v1(54.61,76.835)
  Bottom Layer w2: JP4a.4 6.19,23.846 3.458,23.846 2.286,25.017 2.286,77.187 3.458,78.359 22.27,78.359 v1@23.604,77.025 ; v1(54.61,76.835) 65.376,76.835 66.548,78.007 66.548,84.992 ; 66.548,89.027 66.548,95.856 65.376,97.028 C1a.2 60.539,96.839 60.539,94.936 66.548,88.927 66.548,85.852 66.548,84.992 ; RV1a.2 73.66,80.01 71.541,82.129 71.541,84.059 TR1A.1 71.366,84.099 71.086,83.82 67.72,83.82 66.548,84.992
PGND: CE1a.2 CE2a.2 CE3a.2 CE4a.2 DB1a.2 JP3a.2 R53a.1 | length 447.1
  Bottom Layer w3.5: JP3a.2@12.319,97.155 11.968,97.506 5.733,97.506 3.683,99.557 3.683,103.251 ; DB1a.2 129.896,105.131 ; 3.683,103.251 3.683,124.796 5.733,126.846 5.834,126.846 ; 3.683,103.251 3.81,103.124 8.954,103.124 12.446,103.124 ; 5.834,126.846 9.248,130.261 12.446,133.459 ; 5.834,126.846 9.652,126.846 12.446,126.846 ; 12.446,103.124 12.446,99.871 JP3a.2 R53a.1 23.952,101.074 21.902,103.124 12.446,103.124 ; 12.446,103.124 12.446,126.846 ; 12.446,126.846 12.446,133.459 ; 12.446,126.846 CE1a.2 CE2a.2 CE3a.2 CE4a.2 ; 12.446,133.459 14.496,135.509 129.667,135.509 ; CE4a.2 129.896,120.268 ; CE4a.2 129.896,126.846 ; 129.667,135.509 134.112,131.064 134.112,124.796 ; 129.667,135.509 129.896,135.28 129.896,126.846 ; 129.896,105.131 129.896,120.268 ; 129.896,105.131 134.112,109.347 134.112,124.796 ; 129.896,120.268 129.896,121.666 129.896,126.846 ; 129.896,126.846 132.062,126.846 134.112,124.796
  Bottom Layer w5: JP3a.2@12.319,97.155 JP3a.2
PH: C1a.1 RLY1.1 RLY2.1 RLY3.1 RV1a.1 TR1A.4 | length 220.1
  Bottom Layer w2: RLY1.1 22.987,6.731 ; RLY2.1 23.05,26.352 24.257,27.559 ; RLY3.1@18.542,45.72 RLY3.1 23.085,45.974 ; 77.47,88.138 83.693,81.915 83.693,73.845 RV1a.1@79.393,69.545 ; RV1a.1@79.733,69.545 73.203,69.545 TR1A.4 71.405,71.151 67.087,71.151 55.626,59.69 33.274,59.69 28.165,54.581 28.165,45.974 ; 22.987,6.731 26.994,6.731 28.165,7.903 28.165,27.178 28.165,45.974 ; 22.987,6.731 24.257,8.001 24.257,27.559 ; 23.085,45.974 28.165,45.974 ; 23.085,45.974 24.257,44.802 24.257,27.559 ; 74.041,89.027 74.041,97.028 76.298,97.028 77.47,95.856 77.47,87.757 75.311,87.757 74.041,89.027
pads on no net: RLY1.3 RLY2.3 RLY3.3 ST1.1 ST2.1 ST3.1 ST4.1

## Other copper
Bottom Layer:
  rectangle net 16V: 128.905,4.826 131.826,7.493
  rectangle net 16V: 129.54,6.985 133.35,11.049
  rectangle net 16V: 115.443,3.429 130.429,12.065
  region net NL: 64.48,89.692 67.289,91.696 63.911,96.431 61.102,94.428
  rectangle net NL: 64.389,93.98 66.929,94.869
  rectangle net NL: 60.706,94.361 66.167,96.774
  region net HV: 44.885,91.241 57.658,106.172 48.285,114.19 35.512,99.259
  rectangle net HV: 33.147,91.44 45.466,112.903
  rectangle net HV: 32.004,105.156 33.274,109.474
  rectangle net HV: 33.528,105.156 122.301,110.998
  rectangle net PH: 74.168,88.138 77.089,96.266
  rectangle net PH: 24.257,7.366 27.559,9.017
  rectangle net NetC2a_1: 39.497,63.373 42.926,69.088
  rectangle net NetF2a_2: 110.617,69.723 113.665,79.375
  rectangle net NetDB1a_1: 110.744,87.249 113.919,97.282
  rectangle net LO: 10.795,14.351 14.605,28.321
  rectangle net PGND: 5.207,97.282 12.7,127.127
  region net NetJP2a_2: 138.99,75.946 135.053,75.946 135.053,72.39 138.99,72.39
  region net NetDB2_3: 138.43,60.452 134.493,60.452 134.493,56.896 138.43,56.896
  region net NetDB2_1: 138.382,55.324 134.445,55.324 134.445,51.768 138.382,51.768
  region net NetDB1_3: 138.43,50.292 134.493,50.292 134.493,46.736 138.43,46.736
  region net NetC1_2: 136.906,18.542 132.969,18.542 132.969,14.986 136.906,14.986
  region net 12V: 107.061,4.445 107.061,8.382 103.505,8.382 103.505,4.445
  region net GND5: 101.981,4.445 101.981,8.382 98.425,8.382 98.425,4.445
  region net GND5: 96.901,4.445 96.901,8.382 93.345,8.382 93.345,4.445
  rectangle net NetC3a_2: 5.969,72.644 9.906,76.073
  rectangle net HI: 4.572,37.084 8.509,40.513
  rectangle net LO: 4.445,26.924 8.382,30.353
  rectangle net MED: 4.445,32.004 8.382,35.433
  rectangle net NetF1a_1: 5.842,62.484 9.906,65.913
  rectangle net ERTH: 5.842,67.564 9.906,71.12
  rectangle net NetR2_1: 99.441,31.439 102.87,37.084
  rectangle net NetC1_2: 137.16,17.018 139.495,29.005
  rectangle net 12V: 107.95,61.468 116.078,64.262
  rectangle net 12V: 114.681,59.563 125.984,64.008
  rectangle net GND5: 66.802,37.211 67.818,39.116
  rectangle net 5V: 82.804,4.318 91.821,8.509
  rectangle net 5V: 82.804,4.318 86.614,8.255
  rectangle net MEDC: 72.644,4.064 76.2,8.255
  rectangle net LOC: 77.724,4.318 81.28,8.382
  rectangle net NetLED1a_1: 53.872,3.848 57.154,5.842
  rectangle net HI: 6.731,38.735 14.605,53.213
  rectangle net HV: 7.874,83.947 17.145,90.043
  rectangle net PGND: 8.001,93.853 14.605,100.203
  rectangle net ERTH: 42.545,74.549 51.435,82.55
  rectangle net ERTH: 36.576,73.406 39.497,76.9
  rectangle net ERTH: 40.386,74.168 44.704,80.264
  rectangle net NetC2a_1: 42.672,64.262 51.308,69.596
  rectangle net GND5: 88.858,87.503 95.439,94.352
  rectangle net 12V: 91.44,80.137 93.726,82.55
  rectangle net GND5: 79.375,50.145 102.997,60.452
  rectangle net NetLED3a_1: 53.467,41.021 58.039,44.45
  rectangle net NetD2a_1: 48.006,28.448 52.832,32.004
  rectangle net NetLED2a_1: 53.721,22.804 58.293,24.765
  rectangle net NetD1a_1: 52.959,7.715 57.531,12.827
  rectangle net 5V: 94.996,26.797 97.663,29.845
  rectangle net PGND: 127.254,124.079 128.651,125.476
  rectangle net HV: 20.193,110.236 122.301,120.269
  rectangle net 5V: 86.614,19.177 90.019,31.015
  rectangle net 5V: 87.376,19.431 91.694,26.57
  rectangle net 5V: 98.298,19.71 107.696,28.194
  rectangle net 5V: 90.805,21.082 94.615,31.015
  rectangle net 5V: 93.32,19.964 99.568,28.194
  rectangle net GND5: 95.123,6.477 100.203,14.402
  rectangle net NetJP2a_2: 124.333,75.311 136.398,78.613
  rectangle net 12V: 105.283,2.032 110.998,6.477
  rectangle net 16V: 115.697,23.368 121.856,30.861
  rectangle net PH: 24.13,8.382 28.829,45.974
  rectangle net PGND: 9.652,128.016 11.303,130.048
  rectangle net GND5: 92.964,52.705 102.752,60.062
  rectangle net 16V: 117.983,22.352 122.047,26.162
  region net 16V: 115.56,22.949 117.3,21.426 123.224,28.196 121.484,29.719
  rectangle net 16V: 121.031,21.844 131.699,30.48
  rectangle net 12V: 34.163,2.032 42.545,9.398
  rectangle net 12V: 34.417,18.796 42.799,27.686
  rectangle net 12V: 34.163,40.259 42.545,49.149
  rectangle net PGND: 8.85,97.506 23.495,102.235
  rectangle net PGND: 12.7,128.27 130.429,134.62
  rectangle net PGND: 129.667,108.458 133.223,133.985
  text "MCPS Supply 030523" at 139.827,84.455 h2 r270

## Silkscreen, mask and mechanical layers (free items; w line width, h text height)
Top Overlay:
  lines w0.4: 53.594,76.835 24.892,76.835 ; 66.421,42.799 66.421,44.831 ; 68.145,28.321 68.145,30.353 ; 68.453,10.287 90.932,10.287 ; 72.416,16.637 72.416,17.858 ; 88.858,87.122 88.9,68.58 ; 94.615,47.625 94.615,73.787 ; 97.79,40.513 97.79,73.787 ; 110.871,40.513 110.871,52.578 ; 24.892,76.835 24.892,76.835
  text "+" at 23.114,88.773 h1.52 r90
  text "HV_DC" at 23.114,80.264 h1.52 r90
  text "TRANS OUT" at 132.08,66.167 h1.52 r90
  text "220Vac" at 0.658,56.561 h1.52
  text "AC13" at 132.415,53.551 h1.52 r90
  text "ADJ5" at 89.77,46.882 h2 r90
  text "AC13" at 132.542,43.518 h1.52 r90
  text "AC SUP" at 133.356,38.654 h1.52
  text "HI" at 5.969,18.288 h1.52
  text "MED" at 4.699,14.651 h1.52
  text "DC16" at 130.129,14.424 h1.52 r90
  text "TAP SELECT" at 69.525,12.873 h1.52
  text "+" at 89.154,11.684 h1.52 r90
  text "5V" at 89.408,11.684 h1.52
  text "LO" at 5.588,11.43 h1.52
  text "5V" at 83.323,11.222 h1.52
  text "HIC" at 68.555,11.095 h1.52
  text "+" at 104.394,11.049 h1.52 r90
  text "12V" at 104.648,11.049 h1.52
  text "MEDC" at 72.438,10.968 h1.52
  text "LOC" at 78.443,10.968 h1.52
  text "+" at 130.048,10.795 h1.52 r90
  text "NL" at 5.577,7.793 h1.52
  text "TRANS TAPS" at 2.748,6.888 h1.52 r90
  text "DC5/12" at 112.004,0.54 h1.52 r90
Mechanical 1:
  the board outline again, w0.254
